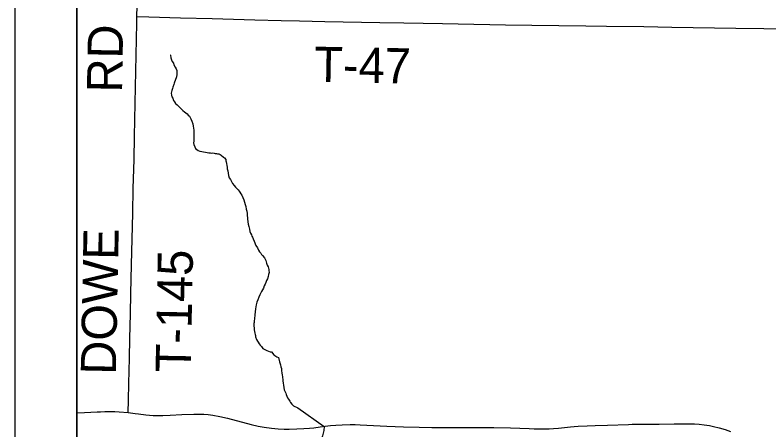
# Model space of a CAD drawing. Extents: x 0 to 34, y 0 to 22.
# Drawn here: x 23.417 to 24.635, y 18.819 to 19.489 of the extents above; entities that cross this region are included whole.
import ezdxf

# ---------------------------------------------------------------- set-up
doc = ezdxf.new("R2010")
doc.units = 0
for name, color, linetype in [('GM_X_Minor_River', 7, 'Continuous'), ('GM_X_Township_Road', 7, 'Continuous'), ('GM_X_Township_Road_Text', 7, 'Continuous'), ('SH_Data', 7, 'Continuous')]:
    doc.layers.add(name, color=color, linetype=linetype)

msp = doc.modelspace()

# ---------------------------------------------------------------- linework, layer by layer
at = {"layer": 'GM_X_Minor_River'}
for points in [[(23.6681, 19.4247), (23.6678, 19.4247), (23.6684, 19.4205), (23.6695, 19.417), (23.6705, 19.4147), (23.6724, 19.412), (23.6734, 19.4089), (23.6752, 19.4055), (23.6767, 19.4028), (23.6782, 19.4001), (23.6781, 19.3971), (23.678, 19.3936), (23.6775, 19.3899), (23.6738, 19.3793), (23.673, 19.3771), (23.6714, 19.3729), (23.671, 19.3707), (23.6697, 19.3676), (23.6689, 19.3635), (23.6692, 19.3601), (23.6699, 19.3574), (23.6713, 19.3551), (23.6728, 19.3516), (23.6742, 19.3493), (23.676, 19.3466), (23.6783, 19.3443), (23.6801, 19.3427), (23.6824, 19.3407), (23.6857, 19.3372), (23.6879, 19.3353), (23.6902, 19.3333), (23.6924, 19.3314), (23.6946, 19.3298), (23.6965, 19.3279), (23.6983, 19.3259), (23.7009, 19.322), (23.7023, 19.3178), (23.7037, 19.3136), (23.7044, 19.3102), (23.7051, 19.3067), (23.7054, 19.3037), (23.7053, 19.3003), (23.7056, 19.2969), (23.7055, 19.2931), (23.7054, 19.2896), (23.7053, 19.2859), (23.7052, 19.2828), (23.7055, 19.2805), (23.707, 19.2767), (23.7084, 19.274), (23.7103, 19.2721), (23.7125, 19.2705), (23.7151, 19.2693), (23.7242, 19.2679), (23.7269, 19.2675), (23.7295, 19.267), (23.7318, 19.2666), (23.7337, 19.2665), (23.7363, 19.2668), (23.7382, 19.2664), (23.7401, 19.266), (23.742, 19.2659), (23.7439, 19.2655), (23.7458, 19.2651), (23.7481, 19.2643), (23.7499, 19.2631), (23.7533, 19.2599), (23.7551, 19.2588), (23.757, 19.2561), (23.7573, 19.2541), (23.7576, 19.2522), (23.7583, 19.2496), (23.7586, 19.2465), (23.7593, 19.2435), (23.7596, 19.2408), (23.7603, 19.2377), (23.7616, 19.2305), (23.7627, 19.2267), (23.7649, 19.2236), (23.7663, 19.2205), (23.7682, 19.2174), (23.7704, 19.2143), (23.7726, 19.2116), (23.7748, 19.2093), (23.777, 19.2069), (23.7789, 19.205), (23.7799, 19.2031), (23.7814, 19.2007), (23.7829, 19.1984), (23.7847, 19.1946), (23.7861, 19.1911), (23.7871, 19.1873), (23.7882, 19.1835), (23.7896, 19.18), (23.7903, 19.1758), (23.7913, 19.1724), (23.7916, 19.1686), (23.7919, 19.1652), (23.7922, 19.1625), (23.7922, 19.1598), (23.7935, 19.1514)], [(23.7935, 19.1514), (23.7941, 19.1476), (23.7952, 19.1434), (23.7962, 19.14), (23.7973, 19.1369), (23.7984, 19.1342), (23.7994, 19.1323), (23.8002, 19.1304), (23.8016, 19.1277), (23.803, 19.1239), (23.8059, 19.1173), (23.8081, 19.1131), (23.8099, 19.1096), (23.8117, 19.1069), (23.8136, 19.1046), (23.815, 19.1027), (23.8165, 19.1007), (23.8195, 19.0972), (23.8216, 19.093), (23.8227, 19.0884), (23.8241, 19.0853), (23.8255, 19.0826), (23.8262, 19.0804), (23.8266, 19.0784), (23.8269, 19.0765), (23.8272, 19.0735), (23.8264, 19.0701), (23.8255, 19.0671), (23.8243, 19.0633), (23.8231, 19.0603), (23.8219, 19.0573), (23.8207, 19.0547), (23.8191, 19.0517), (23.8178, 19.0483), (23.8163, 19.0453), (23.815, 19.0427), (23.8139, 19.0404), (23.8123, 19.0374), (23.8103, 19.0337), (23.809, 19.0291), (23.8074, 19.0258), (23.8066, 19.0235), (23.8062, 19.0212), (23.8057, 19.0178), (23.8052, 19.0148), (23.8042, 19.0053), (23.8038, 19.0031), (23.8037, 19.0008), (23.8033, 18.9985), (23.8028, 18.9955), (23.8028, 18.9928), (23.8024, 18.991), (23.8023, 18.9887), (23.8026, 18.9868), (23.8029, 18.9841), (23.8032, 18.9811), (23.8036, 18.9784), (23.8039, 18.9757), (23.8046, 18.9734), (23.8049, 18.9715), (23.8052, 18.9696), (23.8067, 18.9654), (23.8081, 18.9627), (23.8096, 18.9608), (23.811, 18.9581), (23.8129, 18.9558), (23.8147, 18.9538), (23.8169, 18.9507), (23.8233, 18.9475), (23.8286, 18.9455), (23.8312, 18.9454), (23.8349, 18.9404), (23.8398, 18.9372), (23.8424, 18.936), (23.8441, 18.9291), (23.8455, 18.9242), (23.8462, 18.9211), (23.8469, 18.9184), (23.8472, 18.9146), (23.8478, 18.9112), (23.8481, 18.9078), (23.8485, 18.9055), (23.8488, 18.9032), (23.8491, 18.9013), (23.8494, 18.8982), (23.8497, 18.8944), (23.8504, 18.8914), (23.851, 18.8876), (23.8517, 18.8837), (23.8528, 18.8807), (23.8539, 18.8787), (23.8549, 18.8761), (23.856, 18.8734), (23.8571, 18.8711), (23.8582, 18.8688), (23.8604, 18.8653), (23.8618, 18.8634), (23.864, 18.8606), (23.8666, 18.8579), (23.8734, 18.8547)], [(23.8734, 18.8547), (23.9162, 18.8246)], [(23.9162, 18.8246), (23.9158, 18.8183), (23.9133, 18.8096), (23.912, 18.8047), (23.9095, 18.7968), (23.9056, 18.7908), (23.9029, 18.789), (23.8967, 18.7835), (23.8944, 18.782), (23.8916, 18.7798), (23.8897, 18.7779), (23.8878, 18.7761), (23.8858, 18.7731), (23.8834, 18.7701), (23.8807, 18.7672), (23.8787, 18.7642), (23.8771, 18.7612), (23.8755, 18.7582), (23.8743, 18.7555), (23.8664, 18.7428)]]:
    msp.add_lwpolyline(points, dxfattribs=at)
at = {"layer": 'GM_X_Township_Road'}
for points in [[(28.9104, 20.9), (23.5167, 20.9), (23.5167, 18.4074), (23.5512, 18.4226), (23.5995, 18.4744), (23.627, 18.5353), (23.6328, 18.5687), (23.6269, 18.7216), (23.6395, 18.7618), (23.6866, 18.7918), (23.7407, 18.7883), (23.8186, 18.7551), (23.898, 18.7), (23.9624, 18.631), (24.0257, 18.5782), (24.12, 18.538), (24.1994, 18.53), (24.2856, 18.5622), (24.3637, 18.583), (24.4603, 18.5785), (24.5339, 18.5567), (24.6064, 18.5004), (24.7215, 18.313)], [(23.6136, 19.4871), (23.6144, 19.5216), (23.6152, 19.5657), (23.6161, 19.6117), (23.6173, 19.6589), (23.6177, 19.6769), (23.6178, 19.6841)], [(23.5996, 18.8471), (23.6001, 18.8673), (23.6007, 18.894), (23.6016, 18.935), (23.6022, 18.9667), (23.6032, 19.0065), (23.6037, 19.0394), (23.6048, 19.086), (23.6067, 19.1693), (23.6074, 19.209), (23.6089, 19.2563), (23.6097, 19.2935), (23.6108, 19.347), (23.6133, 19.4762), (23.6136, 19.4871)], [(23.6136, 19.4871), (23.6327, 19.4868), (23.6837, 19.485), (23.7353, 19.4837), (23.8042, 19.4817), (23.8465, 19.4806), (23.8763, 19.4802), (23.9173, 19.4793), (24.0062, 19.4776), (24.0448, 19.4768), (24.1075, 19.4757), (24.1579, 19.4746), (24.184, 19.4742), (24.2089, 19.4738)], [(24.2089, 19.4738), (24.2517, 19.4733), (24.3387, 19.4721), (24.3723, 19.4716), (24.4326, 19.4708), (24.478, 19.4699), (24.5812, 19.4685), (24.6719, 19.4671), (24.7216, 19.4666), (24.8049, 19.4656), (24.841, 19.4651), (24.8748, 19.4645)], [(23.5167, 18.8467), (23.5288, 18.8473), (23.5493, 18.8482), (23.5549, 18.8485), (23.5617, 18.8487), (23.5691, 18.8488), (23.5778, 18.8487), (23.5846, 18.8483), (23.5996, 18.8471)], [(23.5996, 18.8471), (23.6105, 18.8456), (23.616, 18.8449), (23.6278, 18.8436), (23.6396, 18.8426), (23.6465, 18.8423), (23.6552, 18.8423), (23.667, 18.8427), (23.6863, 18.8438), (23.7055, 18.8446), (23.7129, 18.8447), (23.7216, 18.8444), (23.7289, 18.8438), (23.7363, 18.8428), (23.7473, 18.8408), (23.76, 18.8379), (23.7979, 18.8281), (23.8094, 18.8254), (23.8192, 18.8236), (23.831, 18.8219), (23.8415, 18.821), (23.8515, 18.8205), (23.8596, 18.8204), (23.8721, 18.8207), (23.8832, 18.8212), (23.8925, 18.8219), (23.8993, 18.8227), (23.9098, 18.824), (23.9178, 18.825), (23.9264, 18.826), (23.9351, 18.8268), (23.9449, 18.8274), (23.9579, 18.8277), (23.9659, 18.8277), (23.974, 18.8274), (24.0174, 18.8252), (24.0441, 18.824), (24.0696, 18.8233), (24.0901, 18.823), (24.1548, 18.8229), (24.1902, 18.8229), (24.2169, 18.8225), (24.2324, 18.8219), (24.2473, 18.8213), (24.2554, 18.821), (24.2716, 18.8206), (24.2797, 18.8208), (24.2865, 18.8212), (24.2946, 18.8219), (24.3143, 18.8239), (24.3198, 18.8245), (24.3266, 18.8251), (24.3409, 18.8259), (24.3539, 18.8264), (24.3738, 18.8269), (24.4079, 18.8281), (24.4135, 18.8282), (24.4185, 18.8283), (24.4433, 18.8283), (24.4576, 18.8282), (24.4818, 18.8287), (24.5036, 18.8288), (24.5147, 18.8288), (24.5221, 18.8284), (24.5301, 18.8275), (24.5386, 18.8261), (24.5453, 18.8246), (24.5543, 18.8224), (24.5638, 18.8196), (24.5726, 18.8166)]]:
    msp.add_lwpolyline(points, dxfattribs=at)
at = {"layer": 'SH_Data'}
for points in [[(23.4167, 21), (30.4167, 21), (30.4167, 14), (23.4167, 14)], [(23.5167, 20.9), (30.3167, 20.9), (30.3167, 14.1), (23.5167, 14.1)]]:
    msp.add_lwpolyline(points, close=True, dxfattribs=at)

# ---------------------------------------------------------------- texts
at = {"layer": 'GM_X_Township_Road_Text'}
for s, rotation, p in [('RD', 89.0118, (23.5895, 19.364)), ('T-47', 358.9446, (23.8995, 19.3817)), ('DOWE', 88.8631, (23.5795, 18.9079)), ('T-145', 88.8912, (23.7004, 18.9114))]:
    msp.add_text(s, height=0.05682, rotation=rotation, dxfattribs=at).set_placement(p)

doc.saveas('drawing.dxf')
